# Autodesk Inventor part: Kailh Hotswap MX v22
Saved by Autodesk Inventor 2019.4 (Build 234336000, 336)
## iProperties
Created: 2020-04
Part Number: Kailh Hotswap MX v22
Material: Generic
Document SubType Name: Modeling
Designer: Administrator
Density: 1 g/cm^3
Appearance: Default
Author: Administrator
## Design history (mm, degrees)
feature "Body1"
feature "Body2"
feature "Body3"
feature "Body4"
body "Solid1"
body "Solid2"
body "Solid3"
body "Solid4"
